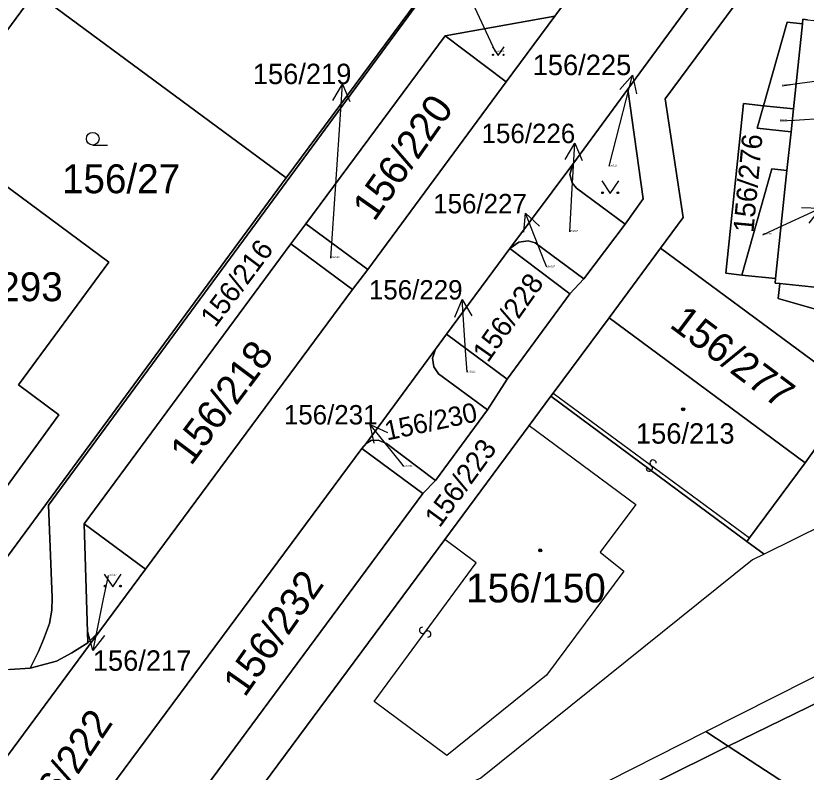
# Model space of a CAD drawing. Extents: x -598233 to -596890, y -1157848 to -1156431.
# Drawn here: x -597550.15 to -597503.64, y -1156884.94 to -1156840.44 of the extents above; entities that cross this region are included whole.
import ezdxf

# ---------------------------------------------------------------- set-up
doc = ezdxf.new("R2010")
doc.units = 0
for name, color, linetype in [('Level 1', 7, 'Continuous'), ('Level 13', 7, 'Continuous'), ('Level 3', 7, 'Continuous'), ('Level 4', 7, 'Continuous'), ('Level 5', 7, 'Continuous'), ('Level 57', 7, 'Continuous'), ('Level 60', 7, 'Continuous'), ('Vrstva 60', 7, 'Continuous')]:
    doc.layers.add(name, color=color, linetype=linetype)

msp = doc.modelspace()

# ---------------------------------------------------------------- linework, layer by layer
at = {"layer": 'Level 1'}
for points in [[(-597549.31, -1156878.82), (-597548.81, -1156877.83), (-597548.51, -1156877.13), (-597548.17, -1156876.19), (-597548.03, -1156875.41), (-597548, -1156874.67), (-597548.22, -1156869.23), (-597526.59, -1156839.83), (-597519.73, -1156838.79), (-597512.5, -1156829.08), (-597512.17, -1156828.42), (-597511.88, -1156827.67), (-597511.49, -1156826.01), (-597511.31, -1156824.45), (-597511.28, -1156822.78), (-597511.45, -1156821.65), (-597512.11, -1156820.25), (-597513.3, -1156819.05)], [(-597507.6, -1156823.12), (-597507.81, -1156824.66), (-597508.35, -1156826.43), (-597508.77, -1156827.33), (-597509.14, -1156827.9), (-597518.43, -1156840.47)], [(-597534.23, -1156849.98), (-597516.65, -1156826.24)], [(-597514.13, -1156844.75), (-597503.91, -1156830.84), (-597503.28, -1156830.06), (-597502.2, -1156829.07), (-597500.85, -1156828.25), (-597499.92, -1156827.88)], [(-597502.47, -1156832.55), (-597511.93, -1156845.32), (-597510.88, -1156852.31), (-597512.21, -1156854.11)], [(-597566.94, -1156863.37), (-597549.03, -1156839.07)], [(-597548.17, -1156839.7), (-597534.23, -1156849.98)], [(-597524.89, -1156841.62), (-597518.43, -1156840.47)], [(-597518.43, -1156840.47), (-597521.29, -1156844.33)], [(-597503.86, -1156840.91), (-597503.83, -1156840.64), (-597503.57, -1156840.67)], [(-597506.15, -1156845.73), (-597504.75, -1156840.82), (-597503.86, -1156840.91)], [(-597503.86, -1156840.91), (-597504.39, -1156845.92)], [(-597533.08, -1156852.68), (-597524.89, -1156841.62)], [(-597521.29, -1156844.33), (-597524.89, -1156841.62)], [(-597521.29, -1156844.33), (-597529.44, -1156855.36)], [(-597514.13, -1156844.75), (-597517.37, -1156849.16)], [(-597514.3, -1156852.69), (-597513.23, -1156851.2), (-597514.13, -1156844.75)], [(-597506.15, -1156845.73), (-597507.32, -1156845.6), (-597508.37, -1156855.59), (-597507.43, -1156855.69)], [(-597506.15, -1156845.73), (-597506.53, -1156847.05), (-597504.53, -1156847.26)], [(-597506.15, -1156845.73), (-597504.39, -1156845.92)], [(-597504.39, -1156845.92), (-597504.53, -1156847.26)], [(-597504.77, -1156849.55), (-597504.53, -1156847.26)], [(-597552.82, -1156848.92), (-597544.68, -1156854.94), (-597549.99, -1156862.15), (-597547.61, -1156863.92), (-597551.28, -1156868.93), (-597556.57, -1156865.09), (-597552.97, -1156860.18), (-597558.25, -1156856.28), (-597552.82, -1156848.92)], [(-597517.37, -1156849.16), (-597521.08, -1156854.14)], [(-597517.37, -1156849.16), (-597517.55, -1156849.77), (-597517.41, -1156850.26), (-597517.16, -1156850.58), (-597514.3, -1156852.69)], [(-597507.43, -1156855.69), (-597505.66, -1156849.45), (-597504.77, -1156849.55)], [(-597505.44, -1156855.9), (-597504.77, -1156849.55)], [(-597534.23, -1156849.98), (-597552.94, -1156875.36)], [(-597533.08, -1156852.68), (-597533.96, -1156853.86)], [(-597529.44, -1156855.36), (-597533.08, -1156852.68)], [(-597516.72, -1156855.92), (-597514.3, -1156852.69)], [(-597521.08, -1156854.14), (-597520.55, -1156853.76), (-597520, -1156853.68), (-597519.58, -1156853.8), (-597516.72, -1156855.92)], [(-597546.12, -1156870.33), (-597533.96, -1156853.86)], [(-597533.96, -1156853.86), (-597530.33, -1156856.54)], [(-597521.08, -1156854.14), (-597524.8, -1156859.17)], [(-597517.54, -1156856.8), (-597521.08, -1156854.14)], [(-597515.24, -1156858.2), (-597512.21, -1156854.11)], [(-597503.71, -1156866.74), (-597500.74, -1156862.59), (-597512.21, -1156854.11)], [(-597530.33, -1156856.54), (-597529.44, -1156855.36)], [(-597516.72, -1156855.92), (-597517.54, -1156856.8)], [(-597505.44, -1156855.9), (-597507.43, -1156855.69)], [(-597505.2, -1156856.19), (-597505.46, -1156856.16), (-597505.44, -1156855.9)], [(-597498.85, -1156856.85), (-597499.06, -1156858.85), (-597505.29, -1156857.07), (-597505.2, -1156856.19)], [(-597498.85, -1156856.85), (-597505.2, -1156856.19)], [(-597530.33, -1156856.54), (-597542.51, -1156873)], [(-597521.24, -1156861.81), (-597517.54, -1156856.8)], [(-597518.53, -1156862.64), (-597515.24, -1156858.2)], [(-597503.71, -1156866.74), (-597515.24, -1156858.2)], [(-597524.8, -1156859.17), (-597525.46, -1156860.06)], [(-597524.8, -1156859.17), (-597521.24, -1156861.81)], [(-597529.53, -1156865.6), (-597525.46, -1156860.06)], [(-597525.46, -1156860.06), (-597525.63, -1156860.58), (-597525.54, -1156861.1), (-597525.27, -1156861.5), (-597522.4, -1156863.62)], [(-597522.4, -1156863.62), (-597521.24, -1156861.81)], [(-597485.46, -1156862.21), (-597487.16, -1156862.76), (-597495.52, -1156866.88), (-597506.12, -1156872.11)], [(-597518.66, -1156862.82), (-597519.94, -1156864.55)], [(-597518.66, -1156862.82), (-597518.53, -1156862.64)], [(-597518.66, -1156862.82), (-597507.13, -1156871.36)], [(-597522.4, -1156863.62), (-597525.46, -1156867.77)], [(-597519.94, -1156864.55), (-597524.91, -1156871.25)], [(-597529.53, -1156865.6), (-597529.78, -1156865.9)], [(-597525.46, -1156867.77), (-597528.33, -1156865.6), (-597528.82, -1156865.41), (-597529.23, -1156865.42), (-597529.53, -1156865.6)], [(-597545, -1156886.43), (-597529.78, -1156865.9)], [(-597529.78, -1156865.9), (-597526.2, -1156868.54)], [(-597506.98, -1156871.16), (-597503.71, -1156866.74)], [(-597526.2, -1156868.54), (-597525.46, -1156867.77)], [(-597526.2, -1156868.54), (-597540.59, -1156888.01)], [(-597542.51, -1156873), (-597546.12, -1156870.33)], [(-597546.12, -1156870.33), (-597545.91, -1156877.33)], [(-597524.91, -1156871.25), (-597538.37, -1156889.43)], [(-597507.13, -1156871.36), (-597506.98, -1156871.16)], [(-597507.13, -1156871.36), (-597506.12, -1156872.11)], [(-597506.12, -1156872.11), (-597506.8, -1156872.44), (-597522.78, -1156885.28), (-597536.09, -1156891.12)], [(-597545.2, -1156876.63), (-597542.51, -1156873)], [(-597509.54, -1156882.55), (-597491.49, -1156873.43)], [(-597508.24, -1156883.41), (-597490.2, -1156874.62)], [(-597545.2, -1156876.63), (-597556.09, -1156891.33)], [(-597545.91, -1156877.33), (-597545.2, -1156876.63)], [(-597549.31, -1156878.82), (-597547.76, -1156878.41), (-597546.85, -1156877.91), (-597545.91, -1156877.33)], [(-597554.46, -1156877.62), (-597553.86, -1156877.97), (-597552.94, -1156878.36), (-597552.1, -1156878.64), (-597550.49, -1156878.9), (-597549.31, -1156878.82)], [(-597522.44, -1156889.07), (-597509.54, -1156882.55)], [(-597509.54, -1156882.55), (-597508.24, -1156883.41)], [(-597521.2, -1156889.86), (-597508.24, -1156883.41)], [(-597508.24, -1156883.41), (-597488.19, -1156896.47)]]:
    msp.add_lwpolyline(points, dxfattribs=at)
at = {"layer": 'Level 13'}
for centre, start, end in [((-597512.649, -1156866.753), 0.9579, 233.0559), ((-597512.87, -1156867.048), 180.7435, 53.3335), ((-597526.207, -1156876.589), 90.9549, 323.0529), ((-597525.912, -1156876.81), 270.7404, 143.3304)]:
    msp.add_arc(centre, 0.184, start, end, dxfattribs=at)
at = {"layer": 'Level 3'}
for points in [[(-597518.53, -1156862.64), (-597506.98, -1156871.16)], [(-597519.94, -1156864.55), (-597513.67, -1156869.18), (-597515.77, -1156872), (-597514.37, -1156873.11), (-597518.92, -1156879.22), (-597524.79, -1156883.95), (-597529.07, -1156880.78), (-597523.05, -1156872.62), (-597524.91, -1156871.25)]]:
    msp.add_lwpolyline(points, dxfattribs=at)
at = {"layer": 'Level 5'}
msp.add_line((-597545.62, -1156848.05), (-597544.745, -1156848.05), dxfattribs=at)
for points in [[(-597522.101, -1156842.26), (-597521.76, -1156842.77), (-597521.42, -1156842.26)], [(-597515.671, -1156850.15), (-597515.17, -1156850.9), (-597514.67, -1156850.15)], [(-597544.941, -1156873.29), (-597544.44, -1156874.04), (-597543.94, -1156873.29)]]:
    msp.add_lwpolyline(points, dxfattribs=at)
for centre, radius in [((-597522.066, -1156842.736), 0.034), ((-597521.455, -1156842.736), 0.034), ((-597545.62, -1156847.675), 0.375), ((-597515.62, -1156850.85), 0.05), ((-597514.721, -1156850.85), 0.05), ((-597510.88, -1156863.59), 0.09), ((-597510.88, -1156863.59), 0.0521), ((-597519.29, -1156871.89), 0.09), ((-597519.29, -1156871.89), 0.0521), ((-597544.89, -1156873.99), 0.05), ((-597543.991, -1156873.99), 0.05)]:
    msp.add_circle(centre, radius, dxfattribs=at)
at = {"layer": 'Level 57'}
for p, q in [((-597521.93, -1156842.57), (-597523.543, -1156839.083)), ((-597514.611, -1156846.836), (-597513.866, -1156843.93)), ((-597504.17, -1156844.433), (-597501.2, -1156844.01)), ((-597531.121, -1156847.453), (-597530.919, -1156844.46)), ((-597505.06, -1156844.56), (-597504.17, -1156844.433)), ((-597505.17, -1156846.62), (-597504.335, -1156846.572)), ((-597504.335, -1156846.572), (-597501.34, -1156846.4)), ((-597515.24, -1156849.29), (-597514.611, -1156846.836)), ((-597531.61, -1156854.69), (-597531.121, -1156847.453)), ((-597517.426, -1156850.925), (-597517.26, -1156847.93)), ((-597517.55, -1156853.15), (-597517.426, -1156850.925)), ((-597505.517, -1156853.011), (-597502.79, -1156851.76)), ((-597519.058, -1156854.853), (-597520.154, -1156852.06)), ((-597506.19, -1156853.32), (-597505.517, -1156853.011)), ((-597518.91, -1156855.23), (-597519.058, -1156854.853)), ((-597523.68, -1156860.123), (-597523.89, -1156857.13)), ((-597523.59, -1156861.41), (-597523.68, -1156860.123)), ((-597527.417, -1156866.826), (-597529.287, -1156864.48)), ((-597527.31, -1156866.96), (-597527.417, -1156866.826)), ((-597544.72, -1156873.37), (-597545.018, -1156874.83)), ((-597545.018, -1156874.83), (-597545.617, -1156877.77))]:
    msp.add_line(p, q, dxfattribs=at)
for points in [[(-597514.599, -1156844.774), (-597513.866, -1156843.93), (-597513.63, -1156845.023)], [(-597531.485, -1156845.424), (-597530.919, -1156844.46), (-597530.487, -1156845.491)], [(-597517.814, -1156848.9), (-597517.26, -1156847.93), (-597516.816, -1156848.956)], [(-597503.908, -1156851.723), (-597502.79, -1156851.76), (-597503.491, -1156852.631)], [(-597520.254, -1156853.174), (-597520.154, -1156852.06), (-597519.323, -1156852.809)], [(-597524.319, -1156858.163), (-597523.89, -1156857.13), (-597523.321, -1156858.093)], [(-597529.055, -1156865.574), (-597529.287, -1156864.48), (-597528.273, -1156864.95)], [(-597544.927, -1156876.89), (-597545.617, -1156877.77), (-597545.907, -1156876.69)]]:
    msp.add_lwpolyline(points, dxfattribs=at)
at = {"layer": 'Level 60'}
for points in [[(-597563.45, -1156782.09), (-597513.3, -1156819.05), (-597512.11, -1156820.25), (-597511.45, -1156821.65), (-597511.28, -1156822.78), (-597511.31, -1156824.45), (-597511.49, -1156826.01), (-597511.88, -1156827.67), (-597512.17, -1156828.42), (-597512.5, -1156829.08), (-597519.73, -1156838.79), (-597526.59, -1156839.83), (-597548.22, -1156869.23), (-597548, -1156874.67), (-597548.03, -1156875.41), (-597548.17, -1156876.19), (-597548.51, -1156877.13), (-597548.81, -1156877.83), (-597549.31, -1156878.82), (-597550.49, -1156878.9)], [(-597552.94, -1156875.36), (-597534.23, -1156849.98), (-597516.65, -1156826.24), (-597513.06, -1156821.39), (-597527.04, -1156811.05), (-597533.48, -1156806.29), (-597539.9, -1156801.53)], [(-597556.09, -1156891.33), (-597545.2, -1156876.63), (-597542.51, -1156873), (-597530.33, -1156856.54), (-597529.44, -1156855.36), (-597521.29, -1156844.33), (-597518.43, -1156840.47), (-597509.14, -1156827.9), (-597508.77, -1156827.33), (-597508.35, -1156826.43), (-597507.81, -1156824.66), (-597507.6, -1156823.12), (-597499.92, -1156827.88)], [(-597509.14, -1156827.9), (-597518.43, -1156840.47), (-597524.89, -1156841.62), (-597533.08, -1156852.68), (-597533.96, -1156853.86), (-597546.12, -1156870.33), (-597545.91, -1156877.33), (-597546.85, -1156877.91), (-597547.76, -1156878.41), (-597549.31, -1156878.82), (-597548.81, -1156877.83), (-597548.51, -1156877.13), (-597548.17, -1156876.19), (-597548.03, -1156875.41), (-597548, -1156874.67), (-597548.22, -1156869.23), (-597526.59, -1156839.83)], [(-597503.28, -1156830.06), (-597503.91, -1156830.84), (-597514.13, -1156844.75), (-597517.37, -1156849.16), (-597521.08, -1156854.14), (-597524.8, -1156859.17), (-597525.46, -1156860.06), (-597529.53, -1156865.6), (-597529.78, -1156865.9), (-597545, -1156886.43), (-597545.21, -1156886.71), (-597555.68, -1156900.85), (-597556.38, -1156901.73), (-597557.51, -1156903.08), (-597571.92, -1156909.74), (-597566.71, -1156912.01), (-597569.06, -1156913.87), (-597572.36, -1156916.15), (-597574.9, -1156917.73), (-597577.53, -1156919.24), (-597580.22, -1156920.61), (-597587.57, -1156923.77), (-597595.87, -1156927.27), (-597606.06, -1156931.56)], [(-597502.47, -1156832.55), (-597511.93, -1156845.32), (-597510.88, -1156852.31), (-597512.21, -1156854.11), (-597515.24, -1156858.2), (-597518.53, -1156862.64), (-597518.66, -1156862.82), (-597519.94, -1156864.55), (-597524.91, -1156871.25), (-597538.37, -1156889.43), (-597540.59, -1156888.01), (-597526.2, -1156868.54), (-597525.46, -1156867.77), (-597522.4, -1156863.62), (-597521.24, -1156861.81), (-597517.54, -1156856.8), (-597516.72, -1156855.92), (-597514.3, -1156852.69), (-597513.23, -1156851.2), (-597514.13, -1156844.75), (-597503.91, -1156830.84), (-597503.28, -1156830.06)], [(-597495.52, -1156866.88), (-597506.12, -1156872.11), (-597507.13, -1156871.36), (-597506.98, -1156871.16), (-597503.71, -1156866.74), (-597500.74, -1156862.59), (-597512.21, -1156854.11), (-597510.88, -1156852.31), (-597511.93, -1156845.32), (-597502.47, -1156832.55)], [(-597503.57, -1156840.67), (-597503.83, -1156840.64), (-597503.86, -1156840.91), (-597504.75, -1156840.82), (-597506.15, -1156845.73), (-597507.32, -1156845.6), (-597508.37, -1156855.59), (-597507.43, -1156855.69), (-597505.44, -1156855.9), (-597505.46, -1156856.16), (-597505.2, -1156856.19), (-597505.29, -1156857.07), (-597499.06, -1156858.85)]]:
    msp.add_lwpolyline(points, dxfattribs=at)
for points in [[(-597530.64, -1156815.92), (-597516.65, -1156826.24), (-597534.23, -1156849.98), (-597548.17, -1156839.7), (-597539.46, -1156827.89), (-597539.17, -1156828.1), (-597538.41, -1156827.08), (-597536.23, -1156828.68), (-597537, -1156829.71), (-597532.8, -1156832.8), (-597532.04, -1156831.77), (-597529.65, -1156833.53), (-597526.19, -1156828.85), (-597528.42, -1156827.18), (-597524.32, -1156821.31), (-597528.48, -1156818.26), (-597529.18, -1156819.2), (-597531.7, -1156817.36)], [(-597563.82, -1156828.16), (-597561.04, -1156830.21), (-597554.61, -1156834.95), (-597549.03, -1156839.07), (-597566.94, -1156863.37), (-597567.99, -1156862.6), (-597557.8, -1156848.71), (-597561.07, -1156846.27), (-597559.43, -1156844.05), (-597562.45, -1156841.83), (-597560.79, -1156839.52), (-597566.19, -1156835.53), (-597567.9, -1156837.83), (-597567.61, -1156838.03), (-597573.05, -1156845.4), (-597573.31, -1156845.17), (-597575.76, -1156848.47), (-597570.13, -1156852.62), (-597571.26, -1156854.14), (-597574.98, -1156859.11), (-597582.53, -1156853.54)], [(-597549.03, -1156839.07), (-597548.17, -1156839.7), (-597534.23, -1156849.98), (-597552.94, -1156875.36), (-597554.09, -1156874.51), (-597559.69, -1156870.38), (-597567.74, -1156864.45), (-597566.94, -1156863.37)], [(-597518.43, -1156840.47), (-597521.29, -1156844.33), (-597524.89, -1156841.62)], [(-597503.86, -1156840.91), (-597503.83, -1156840.64), (-597503.57, -1156840.67), (-597497.22, -1156841.34), (-597494.93, -1156841.58), (-597488.58, -1156842.25), (-597488.32, -1156842.28), (-597488.35, -1156842.54), (-597489.01, -1156848.89), (-597489.25, -1156851.18), (-597489.92, -1156857.53), (-597489.95, -1156857.79), (-597490.21, -1156857.76), (-597496.56, -1156857.1), (-597497.49, -1156857), (-597498.85, -1156856.85), (-597505.2, -1156856.19), (-597505.46, -1156856.16), (-597505.44, -1156855.9), (-597504.77, -1156849.55), (-597504.53, -1156847.26), (-597504.39, -1156845.92)], [(-597504.39, -1156845.92), (-597506.15, -1156845.73), (-597504.75, -1156840.82), (-597503.86, -1156840.91)], [(-597524.89, -1156841.62), (-597521.29, -1156844.33), (-597529.44, -1156855.36), (-597533.08, -1156852.68)], [(-597517.37, -1156849.16), (-597514.13, -1156844.75), (-597513.23, -1156851.2), (-597514.3, -1156852.69), (-597517.16, -1156850.58), (-597517.41, -1156850.26), (-597517.55, -1156849.77)], [(-597504.53, -1156847.26), (-597504.77, -1156849.55), (-597505.66, -1156849.45), (-597507.43, -1156855.69), (-597508.37, -1156855.59), (-597507.32, -1156845.6), (-597506.15, -1156845.73), (-597506.53, -1156847.05)], [(-597506.15, -1156845.73), (-597504.39, -1156845.92), (-597504.53, -1156847.26), (-597506.53, -1156847.05)], [(-597552.82, -1156848.92), (-597544.68, -1156854.94), (-597549.99, -1156862.15), (-597547.61, -1156863.92), (-597551.28, -1156868.93), (-597556.57, -1156865.09), (-597552.97, -1156860.18), (-597558.25, -1156856.28)], [(-597544.68, -1156854.94), (-597552.82, -1156848.92), (-597558.25, -1156856.28), (-597552.97, -1156860.18), (-597556.57, -1156865.09), (-597551.28, -1156868.93), (-597547.61, -1156863.92), (-597549.99, -1156862.15)], [(-597517.37, -1156849.16), (-597517.55, -1156849.77), (-597517.41, -1156850.26), (-597517.16, -1156850.58), (-597514.3, -1156852.69), (-597516.72, -1156855.92), (-597519.58, -1156853.8), (-597520, -1156853.68), (-597520.55, -1156853.76), (-597521.08, -1156854.14)], [(-597504.77, -1156849.55), (-597505.44, -1156855.9), (-597507.43, -1156855.69), (-597505.66, -1156849.45)], [(-597530.33, -1156856.54), (-597533.96, -1156853.86), (-597533.08, -1156852.68), (-597529.44, -1156855.36)], [(-597521.08, -1156854.14), (-597520.55, -1156853.76), (-597520, -1156853.68), (-597519.58, -1156853.8), (-597516.72, -1156855.92), (-597517.54, -1156856.8)], [(-597542.51, -1156873), (-597546.12, -1156870.33), (-597533.96, -1156853.86), (-597530.33, -1156856.54)], [(-597521.08, -1156854.14), (-597517.54, -1156856.8), (-597521.24, -1156861.81), (-597524.8, -1156859.17)], [(-597503.71, -1156866.74), (-597515.24, -1156858.2), (-597512.21, -1156854.11), (-597500.74, -1156862.59)], [(-597505.2, -1156856.19), (-597498.85, -1156856.85), (-597499.06, -1156858.85), (-597505.29, -1156857.07)], [(-597507.13, -1156871.36), (-597518.66, -1156862.82), (-597518.53, -1156862.64), (-597515.24, -1156858.2), (-597503.71, -1156866.74), (-597506.98, -1156871.16)], [(-597524.8, -1156859.17), (-597521.24, -1156861.81), (-597522.4, -1156863.62), (-597525.27, -1156861.5), (-597525.54, -1156861.1), (-597525.63, -1156860.58), (-597525.46, -1156860.06)], [(-597525.46, -1156860.06), (-597525.63, -1156860.58), (-597525.54, -1156861.1), (-597525.27, -1156861.5), (-597522.4, -1156863.62), (-597525.46, -1156867.77), (-597528.33, -1156865.6), (-597528.82, -1156865.41), (-597529.23, -1156865.42), (-597529.53, -1156865.6)], [(-597506.12, -1156872.11), (-597506.8, -1156872.44), (-597522.78, -1156885.28), (-597536.09, -1156891.12), (-597538.37, -1156889.43), (-597524.91, -1156871.25), (-597519.94, -1156864.55), (-597518.66, -1156862.82), (-597507.13, -1156871.36)], [(-597528.33, -1156865.6), (-597525.46, -1156867.77), (-597526.2, -1156868.54), (-597529.78, -1156865.9), (-597529.53, -1156865.6), (-597529.23, -1156865.42), (-597528.82, -1156865.41)], [(-597529.78, -1156865.9), (-597526.2, -1156868.54), (-597540.59, -1156888.01), (-597541.44, -1156889.12), (-597545, -1156886.43)], [(-597545.2, -1156876.63), (-597545.91, -1156877.33), (-597546.12, -1156870.33), (-597542.51, -1156873)], [(-597491.49, -1156873.43), (-597490.2, -1156874.62), (-597508.24, -1156883.41), (-597509.54, -1156882.55)], [(-597508.24, -1156883.41), (-597490.2, -1156874.62), (-597478.61, -1156884.95), (-597488.19, -1156896.47)], [(-597549.31, -1156878.82), (-597547.76, -1156878.41), (-597546.85, -1156877.91), (-597545.91, -1156877.33), (-597545.2, -1156876.63), (-597556.09, -1156891.33), (-597555.59, -1156890.45), (-597555.26, -1156889.33), (-597555.05, -1156887.95), (-597555.13, -1156886.57), (-597555.36, -1156885.55), (-597555.71, -1156884.64), (-597556.26, -1156883.66), (-597557.05, -1156882.7), (-597557.58, -1156883.16), (-597557.92, -1156882.8), (-597554.46, -1156877.62), (-597553.86, -1156877.97), (-597552.94, -1156878.36), (-597552.1, -1156878.64), (-597550.49, -1156878.9)], [(-597521.2, -1156889.86), (-597522.44, -1156889.07), (-597509.54, -1156882.55), (-597508.24, -1156883.41)], [(-597441.48, -1156937.05), (-597443.69, -1156939.71), (-597457.57, -1156930.39), (-597491.58, -1156908.73), (-597521.2, -1156889.86), (-597508.24, -1156883.41), (-597488.19, -1156896.47), (-597472.57, -1156906.65), (-597455.3, -1156918.09), (-597452.86, -1156919.74), (-597437.14, -1156931.54)]]:
    msp.add_lwpolyline(points, close=True, dxfattribs=at)
at = {"layer": 'Vrstva 60'}
for points in [[(-597495.52, -1156866.88), (-597506.12, -1156872.11), (-597506.8, -1156872.44), (-597522.78, -1156885.28)], [(-597522.44, -1156889.07), (-597509.54, -1156882.55), (-597491.49, -1156873.43)]]:
    msp.add_lwpolyline(points, dxfattribs=at)

# ---------------------------------------------------------------- texts
at = {"layer": 'Level 4'}
for s, height, p in [('156/221', 0.1, (-597521.93, -1156842.57)), ('156/212', 0.1, (-597505.06, -1156844.56)), ('156/211', 0.1, (-597505.17, -1156846.62)), ('156/27', 1.7, (-597547.431, -1156850.88)), ('156/225', 0.1, (-597515.24, -1156849.29)), ('156/226', 0.1, (-597517.55, -1156853.15)), ('156/210', 0.1, (-597506.19, -1156853.32)), ('156/219', 0.1, (-597531.61, -1156854.69)), ('156/293', 1.7, (-597555.602, -1156857.23)), ('156/227', 0.1, (-597518.91, -1156855.23)), ('156/229', 0.1, (-597523.59, -1156861.41)), ('156/213', 1.2, (-597513.656, -1156865.61)), ('156/231', 0.1, (-597527.31, -1156866.96)), ('156/150', 1.7, (-597523.65, -1156874.95)), ('156/217', 0.1, (-597544.72, -1156873.37))]:
    msp.add_text(s, height=height, dxfattribs=at).set_placement(p)
for s, height, rotation, p in [('156/220', 1.7, 54.9, (-597529.057, -1156852.602)), ('156/276', 1.2, 84.6, (-597506.747, -1156853.231)), ('156/216', 1.2, 53.1, (-597538.416, -1156858.832)), ('156/228', 1.2, 54.9, (-597522.367, -1156860.896)), ('156/277', 1.7, 323.1, (-597511.748, -1156858.714)), ('156/218', 1.7, 53.1, (-597539.835, -1156866.963)), ('156/230', 1.14, 11.9478, (-597528.31, -1156865.43)), ('156/223', 1.2, 54, (-597525.209, -1156870.604)), ('156/232', 1.7, 54.9, (-597536.677, -1156880.585)), ('156/222', 1.7, 55.8, (-597548.997, -1156888.813))]:
    msp.add_text(s, height=height, rotation=rotation, dxfattribs=at).set_placement(p)
at = {"layer": 'Level 57'}
for s, height, p in [('156/225', 1.2, (-597519.734, -1156843.93)), ('156/219', 1.2, (-597536.201, -1156844.46)), ('156/226', 1.14, (-597522.74, -1156847.93)), ('156/227', 1.14, (-597525.586, -1156852.06)), ('156/229', 1.14, (-597529.37, -1156857.13)), ('156/231', 1.14, (-597534.373, -1156864.48)), ('156/217', 1.2, (-597545.616, -1156878.97))]:
    msp.add_text(s, height=height, dxfattribs=at).set_placement(p)

doc.saveas('drawing.dxf')
